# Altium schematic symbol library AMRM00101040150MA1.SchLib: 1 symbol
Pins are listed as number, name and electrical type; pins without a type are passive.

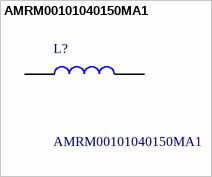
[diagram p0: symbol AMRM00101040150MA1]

## AMRM00101040150MA1
designator L?
15 H Unshielded Inductor 6 A 45mOhm Max Nonstandard; Manufacturer_Name: Yageo Group; Geometry.Height: 4mm
footprint INDPM116102X400N
pins: 1, 2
